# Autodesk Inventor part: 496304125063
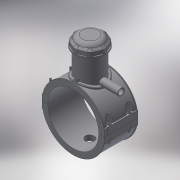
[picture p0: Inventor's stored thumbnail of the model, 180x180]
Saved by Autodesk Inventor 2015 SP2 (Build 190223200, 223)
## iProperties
Created: 2017-07
Part Number: 496304125063
Material: Generic
Description: PLASSON TAPPING SADDLE 125x63
Document SubType Name: Modeling
Designer: KIM
Mass: 1120.34 g
Surface Area: 2443.22 cm^2
Volume: 1120.34 cm^3
Density: 1 g/cm^3
Appearance: Default
Author: KIM
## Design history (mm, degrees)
derived "496304.ipt"
feature "Solid1::496304.ipt"
feature "Solid2::496304.ipt"
feature "Solid4::496304.ipt"
feature "Solid5::496304.ipt"
tag "TaggingFeature1"
body "Solid1"
body "Solid2"
other parameters: "d0" = 125, "d2" = 162, "d3" = 31.25, "d4" = 118, "d5" = 0, "d6" = 0.1, "d8" = 0, "d19" = 6, "d20" = 6, "d21" = 70.8, "d23" = 0, "d24" = 35.4, "d26" = 0, "d29" = 3, "d30" = 41.66667, "d31" = 6, "d32" = 0, "d33" = 0, "d34" = 0.6, "d40" = 78, "d41" = 75, "d43" = 0, "d45" = 0, "d47" = 145.8, "d70" = 15, "d72" = 0, "d73" = 6, "d75" = 5, "d76" = 0, "d77" = 6.25, "d78" = 92.5, "d79" = 15, "d80" = 47.2, "d82" = 5 deg, "d84" = 4, "d85" = 14, "d86" = 0, "d87" = 3, "d88" = 0, "d89" = 1, "d90" = 1, "d91" = 94.4, "d92" = 0, "d93" = 0.5, "d94" = 65.78947, "d96" = 153, "d97" = 2.36, "d98" = 0, "d102" = 1.25, "d120" = 140 deg, "d121" = 24.228, "d122" = 20 deg, "d126" = 0, "d143" = 128.75, "d145" = 19.23077, "d149" = 1.875, "d150" = 21.15385, "d153" = 118, "d154" = 0, "d156" = 75, "d157" = 160 deg, "d159" = 5, "d161" = 1.875, "d162" = 70.8, "d163" = 0, "d164" = 62.5, "d167" = 12.5, "d168" = 73.17073, "d170" = 3.375, "d172" = 0, "d173" = 1, "d175" = 62.5, "d176" = 20 deg, "d177" = 8.75, "d178" = 25, "d180" = 0, "d184" = 7, "d185" = 38.35, "d186" = 38.35, "d187" = 75, "d188" = 7.5, "d189" = 8.75, "d190" = 0, "d191" = 112.5, "d193" = 6.3, "d194" = 4.13, "d195" = 90 deg, "d197" = 0, "d199" = 0, "d200" = 12.5, "d202" = 0, "d203" = 177, "d204" = 71.25, "d205" = 52.5, "d206" = 63.75, "d207" = 132.75, "d208" = 138.06, "d209" = 164.61, "d210" = 64.5, "d211" = 75, "d213" = 29.25, "d216" = 0, "d217" = 12.5, "d218" = 12.5, "d219" = 2.5, "d222" = 125, "d224" = 0, "d230" = 5, "d233" = 6, "d236" = 81, "d237" = 35.4, "d238" = 6.02433, "d240" = 35.4, "d241" = 35.4, "d242" = 35.4, "d243" = 6, "d244" = 35.4, "d245" = 35.4, "d246" = 35.4, "d247" = 6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
